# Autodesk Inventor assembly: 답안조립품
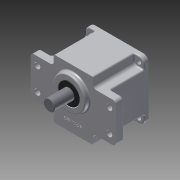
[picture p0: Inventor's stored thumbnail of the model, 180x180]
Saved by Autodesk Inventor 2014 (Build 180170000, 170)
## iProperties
Created: 2015-07
Part Number: 답안조립품
Document SubType Name: Assembly
Designer: Administrator
Author: Administrator
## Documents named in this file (12)
- C:\Users\Administrator\Desktop\450727V1009\답안조립품.iam
- C:\Users\Administrator\Desktop\450727V1009\본체.ipt
- C:\Users\Administrator\Desktop\450727V1009\커버.ipt
- C:\Users\Administrator\Desktop\450727V1009\M4x0.5x16.ipt
- C:\Users\Administrator\Desktop\450727V1009\오일실 17x32x8.ipt
- C:\Users\Administrator\Desktop\450727V1009\오일실 8x22x7.ipt
- C:\Users\Administrator\Desktop\450727V1009\베어링 6003.ipt
- 베어링 6003.ipt
- C:\Users\Administrator\Desktop\450727V1009\베어링 608.ipt
- 베어링 608.ipt
- C:\Users\Administrator\Desktop\450727V1009\서브축.ipt
- C:\Users\Administrator\Desktop\450727V1009\메인축.ipt
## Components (4 placed, 1 different names)
1. M4x0.5x12:1
2. M4x0.5x12:2
3. M4x0.5x12:3
4. M4x0.5x12:4
